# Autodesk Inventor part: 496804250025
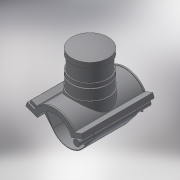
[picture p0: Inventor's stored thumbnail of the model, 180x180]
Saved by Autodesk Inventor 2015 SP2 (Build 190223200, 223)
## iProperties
Created: 2017-07
Part Number: 496804250025
Material: Generic
Description: PLASSON BALLOON SADDLE 250-2.1/2"
Document SubType Name: Modeling
Designer: KIM
Density: 1 g/cm^3
Appearance: Default
Author: KIM
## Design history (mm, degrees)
derived "496804.ipt"
feature "Solid1::496804.ipt"
feature "Solid2::496804.ipt"
tag "TaggingFeature1"
body "Solid1"
body "Solid2"
other parameters: "d1" = 287.5, "d4" = 176, "d5" = 0, "d40" = 149.5, "d96" = 293.25, "d97" = 3.52, "d98" = 0, "d120" = 100 deg, "d121" = 24.228, "d122" = 40 deg, "d123" = 575, "d124" = 172.5, "d126" = 0, "d143" = 257.5, "d145" = 28.84615, "d149" = 3.75, "d150" = 31.73077, "d153" = 176, "d154" = 0, "d159" = 7.5, "d161" = 3.75, "d162" = 105.6, "d163" = 0, "d164" = 125, "d168" = 130.68182, "d170" = 3.75, "d172" = 0, "d173" = 1, "d175" = 125, "d176" = 40 deg, "d180" = 0, "d185" = 57.2, "d186" = 57.2, "d187" = 143.75, "d188" = 11.25, "d190" = 0, "d193" = 7.5, "d194" = 4.4, "d195" = 90 deg, "d197" = 0, "d199" = 0, "d200" = 105, "d201" = 1, "d203" = 94.5, "d204" = 97.65, "d205" = 85.5, "d206" = 1.8, "d207" = 52.5, "d208" = 42, "d209" = 84, "d210" = 21, "d214" = 287.5, "d216" = 0, "d217" = 126, "d220" = 15.98, "d221" = 20 deg, "d223" = 15.3814, "d224" = 7.6907, "d226" = 0, "d227" = -17.6, "d228" = 3.75, "d229" = 55, "B_" = 252, "H_" = 105, "L_" = 176, "d_t" = 6, "d148" = 3.75, "d160" = 3.75, "d169" = 3.75, "d192" = 7.5, "d222" = 19.22675
